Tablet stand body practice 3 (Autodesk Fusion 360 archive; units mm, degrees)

design "mm-Tablet stand body practice 3" references "haas minimill"
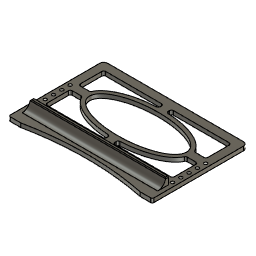
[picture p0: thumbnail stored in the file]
sketch "Sketch1" plane through (0, 0, 0) normal (0, 0, 1) x axis (1, 0, 0)
  line L1 (225.425, 0) -> (0, 0)
  line L2 (225.425, 149.225) -> (225.425, 0)
  line L3 (0, 149.225) -> (225.425, 149.225)
  line L4 (0, 0) -> (0, 149.225)
  point P1 (0, 0)
  point P2 (0, 0)
  point P3 (225.425, 0)
  point P5 (0, 149.225)
  horizontal L1
  vertical L2
  horizontal L3
  vertical L4
  coincident P1 P2
  dimension "d1" distance P2 P3 = 225.425
  dimension "d2" distance P2 P5 = 149.225
extrude "Extrude1" new body sketch "Sketch1" along normal blind 6.35
sketch "Sketch2" plane through (225.425, 0, 0) normal (1, 0, 0) x axis (0, 1, 0)
  line L1 (149.225, 0) -> (0, 0)
  line L2 (149.225, 6.35) -> (149.225, 0)
  line L3 (0, 6.35) -> (149.225, 6.35)
  line L4 (0, 0) -> (0, 6.35)
  line L5 (15.875, 6.35) -> (0, 6.35)
  line L6 (28.575, 6.35) -> (15.875, 6.35)
  line L7 (28.575, 17.907) -> (28.575, 6.35)
  line L8 (31.75, 17.907) -> (28.575, 17.907)
  line L9 (31.75, 6.35) -> (31.75, 17.907)
  line L10 (28.575, 6.35) -> (31.75, 6.35)
  line L11 (27.305, 6.35) -> (28.575, 6.35)
  line L12 (27.305, 16.637) -> (27.305, 6.35)
  line L13 (27.305, 16.637) -> (28.575, 17.907)
  line L14 (34.0111, 17.907) -> (28.575, 17.907)
  point P5 (0, 6.35)
  point P6 (0, 6.35)
  point P11 (31.75, 6.35)
  point P7 (15.875, 6.35)
  point P8 (28.575, 6.35)
  point P9 (28.575, 17.907)
  point P10 (31.75, 17.907)
  point P12 (27.305, 6.35)
  coincident P5 P6
  perpendicular L4 L5
  parallel L3 L6
  perpendicular L6 L7
  perpendicular L7 L8
  coincident L3 P11
  perpendicular L3 L9
  perpendicular L7 L11
  perpendicular L6 L12
  horizontal L14
  dimension "d5" distance P6 P7 = 15.875
  dimension "d6" distance P7 P8 = 12.7
  dimension "d8" distance P8 P9 = 11.557
  dimension "d9" distance P9 P10 = 3.175
  dimension "d10" distance P8 P12 = 1.27
  dimension "d11" angle L13 L14 = 135
extrude "Extrude2" add sketch "Sketch2" profile of L3 L6 L7 L8 L9 L10 L11 L12 L13 against normal blind 225.425
fillet "Fillet1" radius 12.7
sketch "Sketch3" plane through (0, 0, 6.35) normal (0, 0, 1) x axis (-1, 0, 0)
  line L1 (0, -14.8363) -> (-225.425, -14.8363)
  line L2 (0, 0) -> (0, -14.8363)
  line L3 (-225.425, 0) -> (0, 0)
  line L4 (-225.425, -14.8363) -> (-225.425, 0)
  line L5 (-19.05, 0) -> (0, 0)
  line L6 (-206.375, 0) -> (-225.425, 0)
  line L7 (-206.375, 0) -> (-19.05, 0)
  arc A1 centre (-112.7125, 457.2) radius 466.6953 clockwise from (-19.05, 0) to (-206.375, 0)
  point P4 (0, 0)
  point P6 (0, 0)
  point P5 (-225.425, 0)
  point P8 (-225.425, 0)
  point P7 (-19.05, 0)
  point P9 (-206.375, 0)
  point P10 (-112.7125, 457.2)
  coincident P4 P6
  perpendicular L2 L5
  coincident P5 P8
  perpendicular L4 L6
  dimension "d16" distance P6 P7 = 19.05
  dimension "d17" distance P8 P9 = 19.05
  dimension "d18" distance L3 P10 = 457.2
extrude "Extrude3" cut sketch "Sketch3" profile of L3 A1 L7 against normal blind 6.35
sketch "Sketch4" plane through (0, 0, 17.907) normal (0, 0, 1) x axis (-1, 0, 0)
  line L1 (-225.425, -31.75) -> (-225.425, -28.575)
  line L2 (0, -31.75) -> (-225.425, -31.75)
  line L3 (0, -28.575) -> (0, -31.75)
  line L4 (-225.425, -28.575) -> (0, -28.575)
  line L5 (-6.35, -31.75) -> (0, -31.75)
  line L6 (-6.35, -12.7) -> (-6.35, -31.75)
  line L7 (0, -12.7) -> (-6.35, -12.7)
  line L8 (0, -31.75) -> (0, -12.7)
  point P4 (0, -31.75)
  point P6 (0, -31.75)
  point P7 (-6.35, -31.75)
  point P9 (0, -12.7)
  horizontal L5
  vertical L6
  horizontal L7
  vertical L8
  coincident P4 P6
  dimension "d21" distance P6 P7 = 6.35
  dimension "d22" distance P6 P9 = 19.05
work_plane "WorkPlane1"
extrude "Extrude4" cut sketch "Sketch4" profile of L2 L3 L4 L5 L6 L7 L8 to an object
sketch "Sketch5" plane through (0, 0, 17.907) normal (0, 0, 1) x axis (-1, 0, 0)
  line L1 (-6.35, -28.575) -> (-6.35, -31.75)
  line L2 (-225.425, -28.575) -> (-6.35, -28.575)
  line L3 (-225.425, -31.75) -> (-225.425, -28.575)
  line L4 (-6.35, -31.75) -> (-225.425, -31.75)
  line L5 (-219.075, -31.75) -> (-225.425, -31.75)
  line L6 (-219.075, -12.7) -> (-219.075, -31.75)
  line L7 (-225.425, -12.7) -> (-219.075, -12.7)
  line L8 (-225.425, -31.75) -> (-225.425, -12.7)
  point P5 (-225.425, -31.75)
  point P6 (-225.425, -31.75)
  point P7 (-219.075, -31.75)
  point P9 (-225.425, -12.7)
  horizontal L5
  vertical L6
  horizontal L7
  vertical L8
  coincident P5 P6
  dimension "d25" distance P6 P7 = 6.35
  dimension "d26" distance P6 P9 = 19.05
extrude "Extrude5" cut sketch "Sketch5" profile of L2 L3 L4 L5 L6 L7 L8 to an object
chamfer "Chamfer1" distance 1.27
sketch "Sketch6" plane through (0, 0, 6.35) normal (0, 0, 1) x axis (-1, 0, 0)
  line L1 (-225.425, -149.225) -> (-225.425, 0)
  line L2 (0, -149.225) -> (-225.425, -149.225)
  line L3 (0, 0) -> (0, -149.225)
  line L4 (-19.05, 0) -> (0, 0)
  line L5 (-225.425, 0) -> (-206.375, 0)
  line L6 (-219.075, -14.8363) -> (-219.075, -31.75)
  line L7 (-6.35, -14.8363) -> (-219.075, -14.8363)
  line L8 (-6.35, -31.75) -> (-6.35, -14.8363)
  line L9 (-219.075, -31.75) -> (-6.35, -31.75)
  line L10 (-112.7125, -31.75) -> (-112.7125, -149.225)
  line L11 (-225.425, -90.4875) -> (-112.7125, -90.4875)
  curve K1 (-188.9125, -90.4875) -> (-36.5125, -90.4875)
  curve K2 (-112.7125, -122.2375) -> (-112.7125, -58.7375)
  arc A1 centre (-112.7125, 457.2) radius 466.6953 clockwise from (-19.05, 0) to (-206.375, 0)
  closed curve K3 centre (-112.7125, -90.4875)
  point P13 (-112.7125, -149.225)
  point P14 (-112.7125, -31.75)
  point P15 (-112.7125, -90.4875)
  point P18 (-36.5125, -90.4875)
  point P19 (-188.9125, -90.4875)
  point P20 (-112.7125, -58.7375)
  point P21 (-112.7125, -122.2375)
  point P17 (-112.7125, -90.4875)
  point P16 (-225.425, -90.4875)
  midpoint L2 P13
  midpoint L9 P14
  midpoint L10 P15
  perpendicular L10 L11
  coincident K3 P18
  coincident K3 P19
  coincident K3 P20
  coincident K3 P21
  coincident P15 P17
  perpendicular L10 K1
  coincident L1 P16
  dimension "d37" distance K3 = 152.4
  dimension "d38" = 31.75
extrude "Extrude6" cut sketch "Sketch6" profile of L10 L11 K3 no distance stored
sketch "Sketch7" plane through (0, 0, 6.35) normal (0, 0, 1) x axis (-1, 0, 0)
  line L1 (-212.725, -136.525) -> (-12.7, -136.525)
  line L2 (-212.725, -44.45) -> (-212.725, -136.525)
  line L3 (-12.7, -44.45) -> (-212.725, -44.45)
  line L4 (-12.7, -136.525) -> (-12.7, -44.45)
  line L5 (-225.425, -149.225) -> (-225.425, 0)
  line L6 (0, -149.225) -> (-225.425, -149.225)
  line L7 (0, 0) -> (0, -149.225)
  line L8 (-19.05, 0) -> (0, 0)
  line L9 (-225.425, 0) -> (-206.375, 0)
  line L10 (-219.075, -14.8363) -> (-219.075, -31.75)
  line L11 (-6.35, -14.8363) -> (-219.075, -14.8363)
  line L12 (-6.35, -31.75) -> (-6.35, -14.8363)
  line L13 (-219.075, -31.75) -> (-6.35, -31.75)
  line L14 (-106.3625, -90.4875) -> (-112.7125, -90.4875)
  line L15 (-112.7125, -44.45) -> (-112.7125, -90.4875)
  line L16 (-112.7125, -136.525) -> (-112.7125, -90.4875)
  line L17 (-106.3625, -84.1375) -> (-106.3625, -90.4875)
  line L18 (-106.3625, -44.45) -> (-106.3625, -52.5004)
  line L19 (-119.0625, -84.1375) -> (-119.0625, -90.4875)
  line L20 (-119.0625, -44.45) -> (-119.0625, -52.5004)
  line L21 (-106.3625, -122.1271) -> (-106.3625, -90.4875)
  line L22 (-106.3625, -136.525) -> (-106.3625, -128.4746)
  line L23 (-119.0625, -122.1271) -> (-119.0625, -90.4875)
  line L24 (-119.0625, -136.525) -> (-119.0625, -128.4746)
  line L25 (-119.0625, -84.1375) -> (-112.7125, -84.1375)
  line L26 (-212.725, -84.1375) -> (-194.1079, -84.1375)
  line L27 (-119.0625, -96.8375) -> (-112.7125, -96.8375)
  line L28 (-212.725, -96.8375) -> (-194.1079, -96.8375)
  line L29 (-119.0625, -90.4875) -> (-112.7125, -90.4875)
  line L30 (-195.2625, -90.4875) -> (-188.9125, -90.4875)
  line L31 (-38.0521, -84.1375) -> (-112.7125, -84.1375)
  line L32 (-12.7, -84.1375) -> (-31.3171, -84.1375)
  line L33 (-38.0521, -96.8375) -> (-112.7125, -96.8375)
  line L34 (-12.7, -96.8375) -> (-31.3171, -96.8375)
  closed curve K1 centre (-112.7125, -90.4875)
  arc A1 centre (-112.7125, 457.2) radius 466.6953 clockwise from (-19.05, 0) to (-206.375, 0)
  closed curve K2 centre (-112.7125, -90.4875)
  closed curve K3 centre (-112.7125, -90.4875)
  point P6 (-112.7125, -90.4875)
  point P20 (-112.7125, -90.4875)
  point P18 (-112.7125, -90.4875)
  point P21 (-112.7125, -90.4875)
  point P22 (-112.7125, -44.45)
  point P23 (-112.7125, -90.4875)
  point P24 (-112.7125, -136.525)
  point P39 (-106.3625, -84.1375)
  point P41 (-119.0625, -52.5004)
  point P42 (-106.3625, -52.5004)
  point P43 (-106.3625, -122.1271)
  point P44 (-106.3625, -128.4746)
  point P45 (-119.0625, -122.1271)
  point P46 (-119.0625, -128.4746)
  point P47 (-119.0625, -96.8375)
  point P48 (-194.1079, -96.8375)
  point P49 (-194.1079, -84.1375)
  point P50 (-188.9125, -90.4875)
  point P51 (-195.2625, -90.4875)
  point P52 (-38.0521, -84.1375)
  point P53 (-31.3171, -84.1375)
  point P54 (-38.0521, -96.8375)
  point P55 (-31.3171, -96.8375)
  horizontal L1
  vertical L2
  horizontal L3
  vertical L4
  coincident P6 P20
  perpendicular L2 L29
  coincident P18 P21
  midpoint L3 P22
  perpendicular L3 L15
  coincident P18 P23
  midpoint L1 P24
  coincident P39 L31
  collinear L17 L18
  collinear L19 L20
  coincident K3 P41
  coincident K3 P42
  coincident K1 P43
  coincident K3 P44
  collinear L21 L22
  coincident K1 P45
  coincident K3 P46
  collinear L23 L24
  collinear L25 L26
  coincident L23 P47
  collinear L27 L28
  coincident K3 P48
  coincident K3 P49
  coincident K1 P50
  collinear L29 L30
  coincident K3 P51
  coincident K1 P52
  coincident K3 P53
  collinear L31 L32
  coincident K1 P54
  coincident K3 P55
  collinear L33 L34
  dimension "d65" distance L1 L6 = 12.7
  dimension "d66" distance L2 L5 = 12.7 (= "d65")
  dimension "d67" distance L3 L13 = 12.7
  dimension "d68" = 38.1
extrude "Extrude7" cut sketch "Sketch7" profile of L1 L2 L3 L4 K3 L24 L22 L26 L32 L28 L34 L18 L20 no distance stored
fillet "Fillet2" radius 3
fillet "Fillet3" radius 3
hole "Hole1" HoleDepth 35.56 HoleDiameter 5.035 TipAngle 118 RefDim1 6.35 RefDim2 38.1
rectangular_pattern "R-Pattern1" uSpaceDistance -52.07 vSpaceDistance 212.725
fillet "Fillet4" radius 6
fillet "Fillet5" radius 2.5
fillet "Fillet6" radius 2.5
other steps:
thread "Thread1"

design "haas minimill"
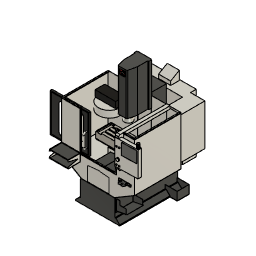
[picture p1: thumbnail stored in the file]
